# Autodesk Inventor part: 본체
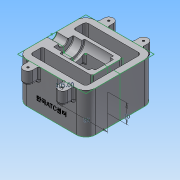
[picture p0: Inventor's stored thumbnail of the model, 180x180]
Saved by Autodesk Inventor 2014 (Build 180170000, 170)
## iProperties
Created: 2018-01
Part Number: 본체
Material: 알루미늄 6061
Document SubType Name: Modeling
Designer: 601-25
Density: 2.71 g/cm^3
Appearance: 알루미늄 - 평지
Mass: 995.137 g
Surface Area: 835.914 cm^2
Volume: 367.209 cm^3
Author: 601-25
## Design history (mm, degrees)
sketch "스케치1"
  geometry: L1 (55, -55)-(-55, -55); L2 (-55, -55)-(-55, 55); L3 (-55, 55)-(55, 55); L4 (55, 55)-(55, -55); L5 (55, -55)-(-55, 55); L6 (-55, -55)-(55, 55); 1 further point
  constraints: 12 end point, 2 midpoint, 2 parallel, 1 horizontal, 1 perpendicular
  dimensions: "d0" = 110 distance of L2.end L3.end; "d1" = 110 distance of L1.end L2.end
extrude "돌출1" new body sketch "스케치1" stored distance "d2" = 65; taper "d3" = 0 deg
sketch "스케치2"
  geometry: L1 (-55, -55)-(55, -55) reference; L2 (55, -55)-(55, 55) reference; L3 (55, 55)-(-55, 55) reference; L4 (-55, 55)-(-55, -55) reference; 1 further point
fillet "모깎기1" dims "d4" = 15
sketch "스케치3" dims "d10" = 0
  geometry: L1 (-55, 40)-(-55, -40) reference; L2 (45, 25)-(-45, 25); L3 (-45, 25)-(-45, 45); L4 (-45, 45)-(45, 45); L5 (45, 45)-(45, 25); L6 (45, 25)-(-45, 45); L7 (-45, 25)-(45, 45); L8 (-40, 55)-(40, 55) reference; 7 further points
  constraints: 12 end point, 8 point on line, 5 horizontal, 4 vertical, 3 midpoint, 2 parallel, 1 perpendicular, 1 vertical alignment, 16 other
  dimensions: "d7" = 10 distance between parallel lines of L4 L8; "d8" = 10 distance between parallel lines of L3 L1; "d9" = 20 distance of L7.start L6.end
extrude "돌출2" cut sketch "스케치3" stored distance "d11" = 65; taper "d12" = 0 deg
sketch "스케치4"
  geometry: L1 (55, -40)-(55, 40) reference; L2 (42, -45)-(35, -45); L3 (35, -45)-(35, 45); L4 (35, 45)-(40, 45); L5 (45, 40)-(45, -42); L6 (45, -45)-(35, 45); L7 (35, -45)-(45, 45); A1 r 5 centre (40, 40) between (45, 40) and (40, 45); A2 r 3 centre (42, -42) between (42, -45) and (45, -42); 3 further points
  constraints: 12 end point, 4 point on circle, 4 point on line, 4 tangent, 3 midpoint, 2 centre point, 2 parallel, 1 horizontal, 1 horizontal alignment, 1 perpendicular
  dimensions: "d16" = 10 distance between parallel lines of L1 L5; "d17" = 20 distance between parallel lines of L1 L3; "d18" = 90 distance of L7.end L6.start; "d19" = 5 radius of A1; "d20" = 3 radius of A2
extrude "돌출3" cut sketch "스케치4" stored distance "d21" = 65; taper "d22" = 0 deg
sketch "스케치6"
  geometry: L1 (0, 80)-(0, 0) reference; C1 r 7.5 at (0, 40); 1 further point
  constraints: 1 centre point, 1 midpoint
  dimensions: "d24" = 15 diameter of C1
extrude "돌출4" cut sketch "스케치6" distance "d25" = 19; taper "d26" = 0 deg
sketch "스케치7"
  geometry: C1 r 16 at (0, 40); A1 r 7.5 centre (0, 40) between (0, 47.5) and (0, 32.5) reference; 1 further point
  constraints: 1 centre point, 1 coincident
  dimensions: "d27" = 32 diameter of C1
extrude "돌출5" cut sketch "스케치7" distance "d28" = 14; taper "d29" = 0 deg
sketch "스케치8"
  geometry: C1 r 20 at (0, 40); A1 r 16 centre (0, 40) between (0, 56) and (0, 24) reference; 1 further point
  constraints: 1 centre point, 1 coincident
  dimensions: "d30" = 40 diameter of C1
extrude "돌출6" cut sketch "스케치8" distance "d31" = 47; taper "d32" = 0 deg
sketch "스케치9"
  geometry: C1 r 15 at (0, 40); A1 r 20 centre (0, 40) between (0, 60) and (0, 20) reference; 1 further point
  constraints: 1 centre point, 1 coincident
  dimensions: "d33" = 30 diameter of C1
extrude "돌출7" cut sketch "스케치9" distance "d34" = 5; taper "d35" = 0 deg
sketch "스케치10"
  geometry: L1 (65, 80)-(65, 47.5) reference; L2 (0, 80)-(65, 80) reference; L3 (0, 0)-(0, 80) reference; L4 (65, 0)-(0, 0) reference; L5 (65, 32.5)-(65, 0) reference; A1 r 7.5 centre (65, 40) between (65, 47.5) and (65, 32.5) reference; 1 further point
sketch "스케치11"
  geometry: L1 (-22, 16)-(-22, 20) reference; L2 (20, -15)-(-17, -15); L3 (-17, -15)-(-17, 15); L4 (-17, 15)-(20, 15); L5 (20, 15)-(20, -15); L6 (20, -15)-(-17, 15); L7 (-17, -15)-(20, 15); 3 further points
  constraints: 12 end point, 3 midpoint, 2 parallel, 1 horizontal, 1 horizontal alignment, 1 perpendicular
  dimensions: "d36" = 37 distance of L3.end L4.end; "d37" = 30 distance of L2.end L3.end; "d38" = 5 distance between parallel lines of L3 L1
sketch "스케치12"
  geometry: L1 (40, 55)-(-40, 55) reference; L2 (-55, 40)-(-55, 7.5) reference; L3 (-35.5, 65)-(-35.5, 55); L4 (-20.5, 65)-(-20.5, 55); L5 (-35.5, 55)-(-20.5, 55); A1 r 7.5 centre (-28, 65) between (-20.5, 65) and (-35.5, 65); 1 further point
  constraints: 6 end point, 2 perpendicular, 2 point on circle, 2 point on line, 2 tangent, 1 centre point, 1 collinear
  dimensions: "d39" = 7.5 radius of A1; "d40" = 27 distance from line of A1.centre L2; "d41" = 10 distance from line of L1 A1.centre
extrude "돌출8" join sketch "스케치12" distance "d42" = 20; taper "d43" = 0 deg
sketch "스케치13"
  geometry: L1 (65, 80)-(65, 47.5) reference; L2 (0, 80)-(65, 80) reference; L3 (0, 0)-(0, 80) reference; L4 (65, 0)-(0, 0) reference; L5 (65, 32.5)-(65, 0) reference; A1 r 7.5 centre (65, 40) between (65, 47.5) and (65, 32.5) reference; 1 further point
sketch "스케치14"
  geometry: L1 (45, -45)-(-45, -45) reference; L2 (-45, -45)-(-45, 45) reference; L3 (-45, 45)-(45, 45) reference; L4 (45, 45)-(45, 25) reference; L5 (45, 25)-(-35, 25) reference; L6 (-35, 25)-(-35, -25) reference; L7 (-35, -25)-(45, -25) reference; L8 (45, -25)-(45, -45) reference; L9 (-55, 40)-(-55, -40) reference; L10 (-40, -55)-(40, -55) reference; L11 (55, -40)-(55, 40) reference; L12 (40, 55)-(-40, 55) reference; A1 r 15 centre (-40, 40) between (-40, 55) and (-55, 40) reference; A2 r 15 centre (-40, -40) between (-55, -40) and (-40, -55) reference; A3 r 15 centre (40, -40) between (40, -55) and (55, -40) reference; A4 r 15 centre (40, 40) between (55, 40) and (40, 55) reference; 1 further point
extrude "돌출9" cut sketch "스케치11" distance "d44" = 35; taper "d45" = 0 deg
sketch "스케치22"
  geometry: L1 (-20, -2.5)-(55, -22.596); L2 (-55, 32.5)-(-45, 32.5) reference; L3 (-45, 32.5)-(-45, -32.5) reference; L4 (-45, -32.5)-(-55, -32.5) reference; L5 (-55, -32.5)-(-55, 32.5) reference; L6 (36, 16.5)-(36, 25) reference; L7 (36, 25)-(55, 25) reference; L8 (55, 25)-(55, -32.5) reference; L9 (55, -32.5)-(-35, -32.5) reference; L10 (-35, -32.5)-(-35, 32.5) reference; L11 (-35, 32.5)-(-30, 32.5) reference; L12 (-30, 32.5)-(-30, 17.5) reference; L13 (-30, 17.5)-(-25, 17.5) reference; L14 (-25, 17.5)-(-25, 12.5) reference; L15 (-25, 12.5)-(-20, 12.5) reference; L16 (-20, 12.5)-(-20, -2.5) reference; L17 (-20, -2.5)-(17, -2.5) reference; L18 (17, -2.5)-(17, 12.5) reference; L19 (17, 12.5)-(22, 12.5) reference; L20 (22, 12.5)-(22, 16.5) reference; L21 (22, 16.5)-(36, 16.5) reference; L22 (55, -4.596)-(17, 5.586); L23 (55, -4.596)-(55, -22.596); L24 (17, 5.586)-(17, -2.5); L25 (17, -2.5)-(-20, -2.5); L26 (-20, -2.5)-(17, -2.5) reference; 1 further point
  constraints: 10 end point, 3 collinear, 3 point on line, 1 parallel
  dimensions: "d73" = 75 deg angle of L8 L1; "d74" = 18 distance of L1.end L22.start
  node "절단 모서리 투영4"
extrude "돌출12" cut sketch "스케치22" distance "d75" = 15; taper "d76" = 0 deg
extrude "돌출13" cut sketch "스케치22" distance "d77" = 15; taper "d78" = 0 deg
sketch "스케치27"
  geometry: A1 r 7.5 centre (-28, 65) between (-20.5, 65) and (-35.5, 65) reference; 2 further points
  constraints: 1 coincident
hole "구멍1" sketch "스케치27" at (-28, 65) diameter "d89" = 3.242; stored, may be unused: countersink angle "d93" = 90 deg, drill point angle "d95" = 118 deg; dims "d90" = 9, "d91" = 4, "d92" = 2, "d94" = 11
sketch "스케치28"
  geometry: L1 (80, 0)-(0, 0) reference; L2 (-15, 65)-(-15, 0) reference; 2 further points
  constraints: 1 other
  dimensions: "d96" = 20 distance from line of L1 point (40, 20); "d97" = 55 distance from line of L2 point (40, 20)
feature "엠보싱1" sketch "스케치28" dims "d98" = 0.5, "d99" = 0
sketch "스케치29"
  geometry: L1 (0, -50)-(65, -50) reference; L2 (65, 0)-(65, -50) reference; L3 (0, 0)-(65, 0) reference; L4 (0, -50)-(0, 0) reference; 1 further point
fillet "모깎기2" dims "d100" = 5
fillet "모깎기3" dims "d101" = 3
fillet "모깎기4" dims "d102" = 3
fillet "모깎기5" dims "d103" = 3
fillet "모깎기6" dims "d107" = 1
chamfer "모따기2" distance "d108" = 1; stored, may be unused: second distance "d109" = 2, angle "d110" = 45 deg
fillet "모깎기7" dims "d117" = 3
sketch "스케치32"
  geometry: L1 (-55, 32.5)-(-45, 32.5) reference; L2 (-45, 32.5)-(-45, -32.5) reference; L3 (-45, -32.5)-(-55, -32.5) reference; L4 (-55, -32.5)-(-55, 32.5) reference; L5 (22, 13.5)-(22, 16.5) reference; L6 (22, 16.5)-(35, 16.5) reference; L7 (36, 17.5)-(36, 24) reference; L8 (36, 24)-(37, 25) reference; L9 (37, 25)-(54, 25) reference; L10 (54, 25)-(55, 24) reference; L11 (55, 24)-(55, -4.596) reference; L12 (55, -4.596)-(17, 5.586) reference; L13 (17, 5.586)-(17, 12.5) reference; L14 (17, 12.5)-(21, 12.5) reference; L15 (-29, 17.5)-(-25, 17.5) reference; L16 (-25, 17.5)-(-25, 13.5) reference; L17 (-24, 12.5)-(-20, 12.5) reference; L18 (-20, 12.5)-(-20, -2.5) reference; L19 (-20, -2.5)-(55, -22.596) reference; L20 (55, -22.596)-(55, -32.5) reference; L21 (55, -32.5)-(-35, -32.5) reference; L22 (-35, -32.5)-(-35, 32.5) reference; L23 (-35, 32.5)-(-30, 32.5) reference; L24 (-30, 32.5)-(-30, 18.5) reference; L25 (-40, 32.5)-(-40, -32.5) reference; L26 (-35, -2.5)-(45, -23.936); L27 (45, -23.936)-(45, -32.5); A1 r 1 centre (21, 13.5) between (21, 12.5) and (22, 13.5) reference; A2 r 1 centre (35, 17.5) between (35, 16.5) and (36, 17.5) reference; A3 r 1 centre (-29, 18.5) between (-30, 18.5) and (-29, 17.5) reference; A4 r 1 centre (-24, 13.5) between (-25, 13.5) and (-24, 12.5) reference; 1 further point
  constraints: 4 end point, 2 point on line, 1 perpendicular
  dimensions: "d119" = 30 distance of L21.end L26.start; "d120" = 105 deg angle of L27 L26; "d126" = 80 horizontal distance of L26.end L26.start
  node "절단 모서리 투영8"
sketch "스케치34"
  geometry: 1 further point
extrude "돌출16" cut sketch "스케치32" stored distance "d124" = 50; taper "d125" = 0 deg
fillet "모깎기10" dims "d129" = 3
fillet "모깎기11" dims "d130" = 3
fillet "모깎기12" dims "d131" = 5
node "솔리드1"
mirror "대칭1"
mirror "대칭2"
mirror "대칭3"
mirror "대칭4"
mirror "대칭5"
